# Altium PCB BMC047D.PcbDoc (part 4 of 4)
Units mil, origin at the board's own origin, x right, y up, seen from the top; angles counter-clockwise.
Board outline 4950 x 3450 mil, 6 copper layers (Top Layer, GND Layer 1, Signal Layer 1, Signal Layer 2, GND Layer 2, Bottom Layer), stack 60.7 mil thick; 323 components, 167 nets, 1114 pads, 795 vias.
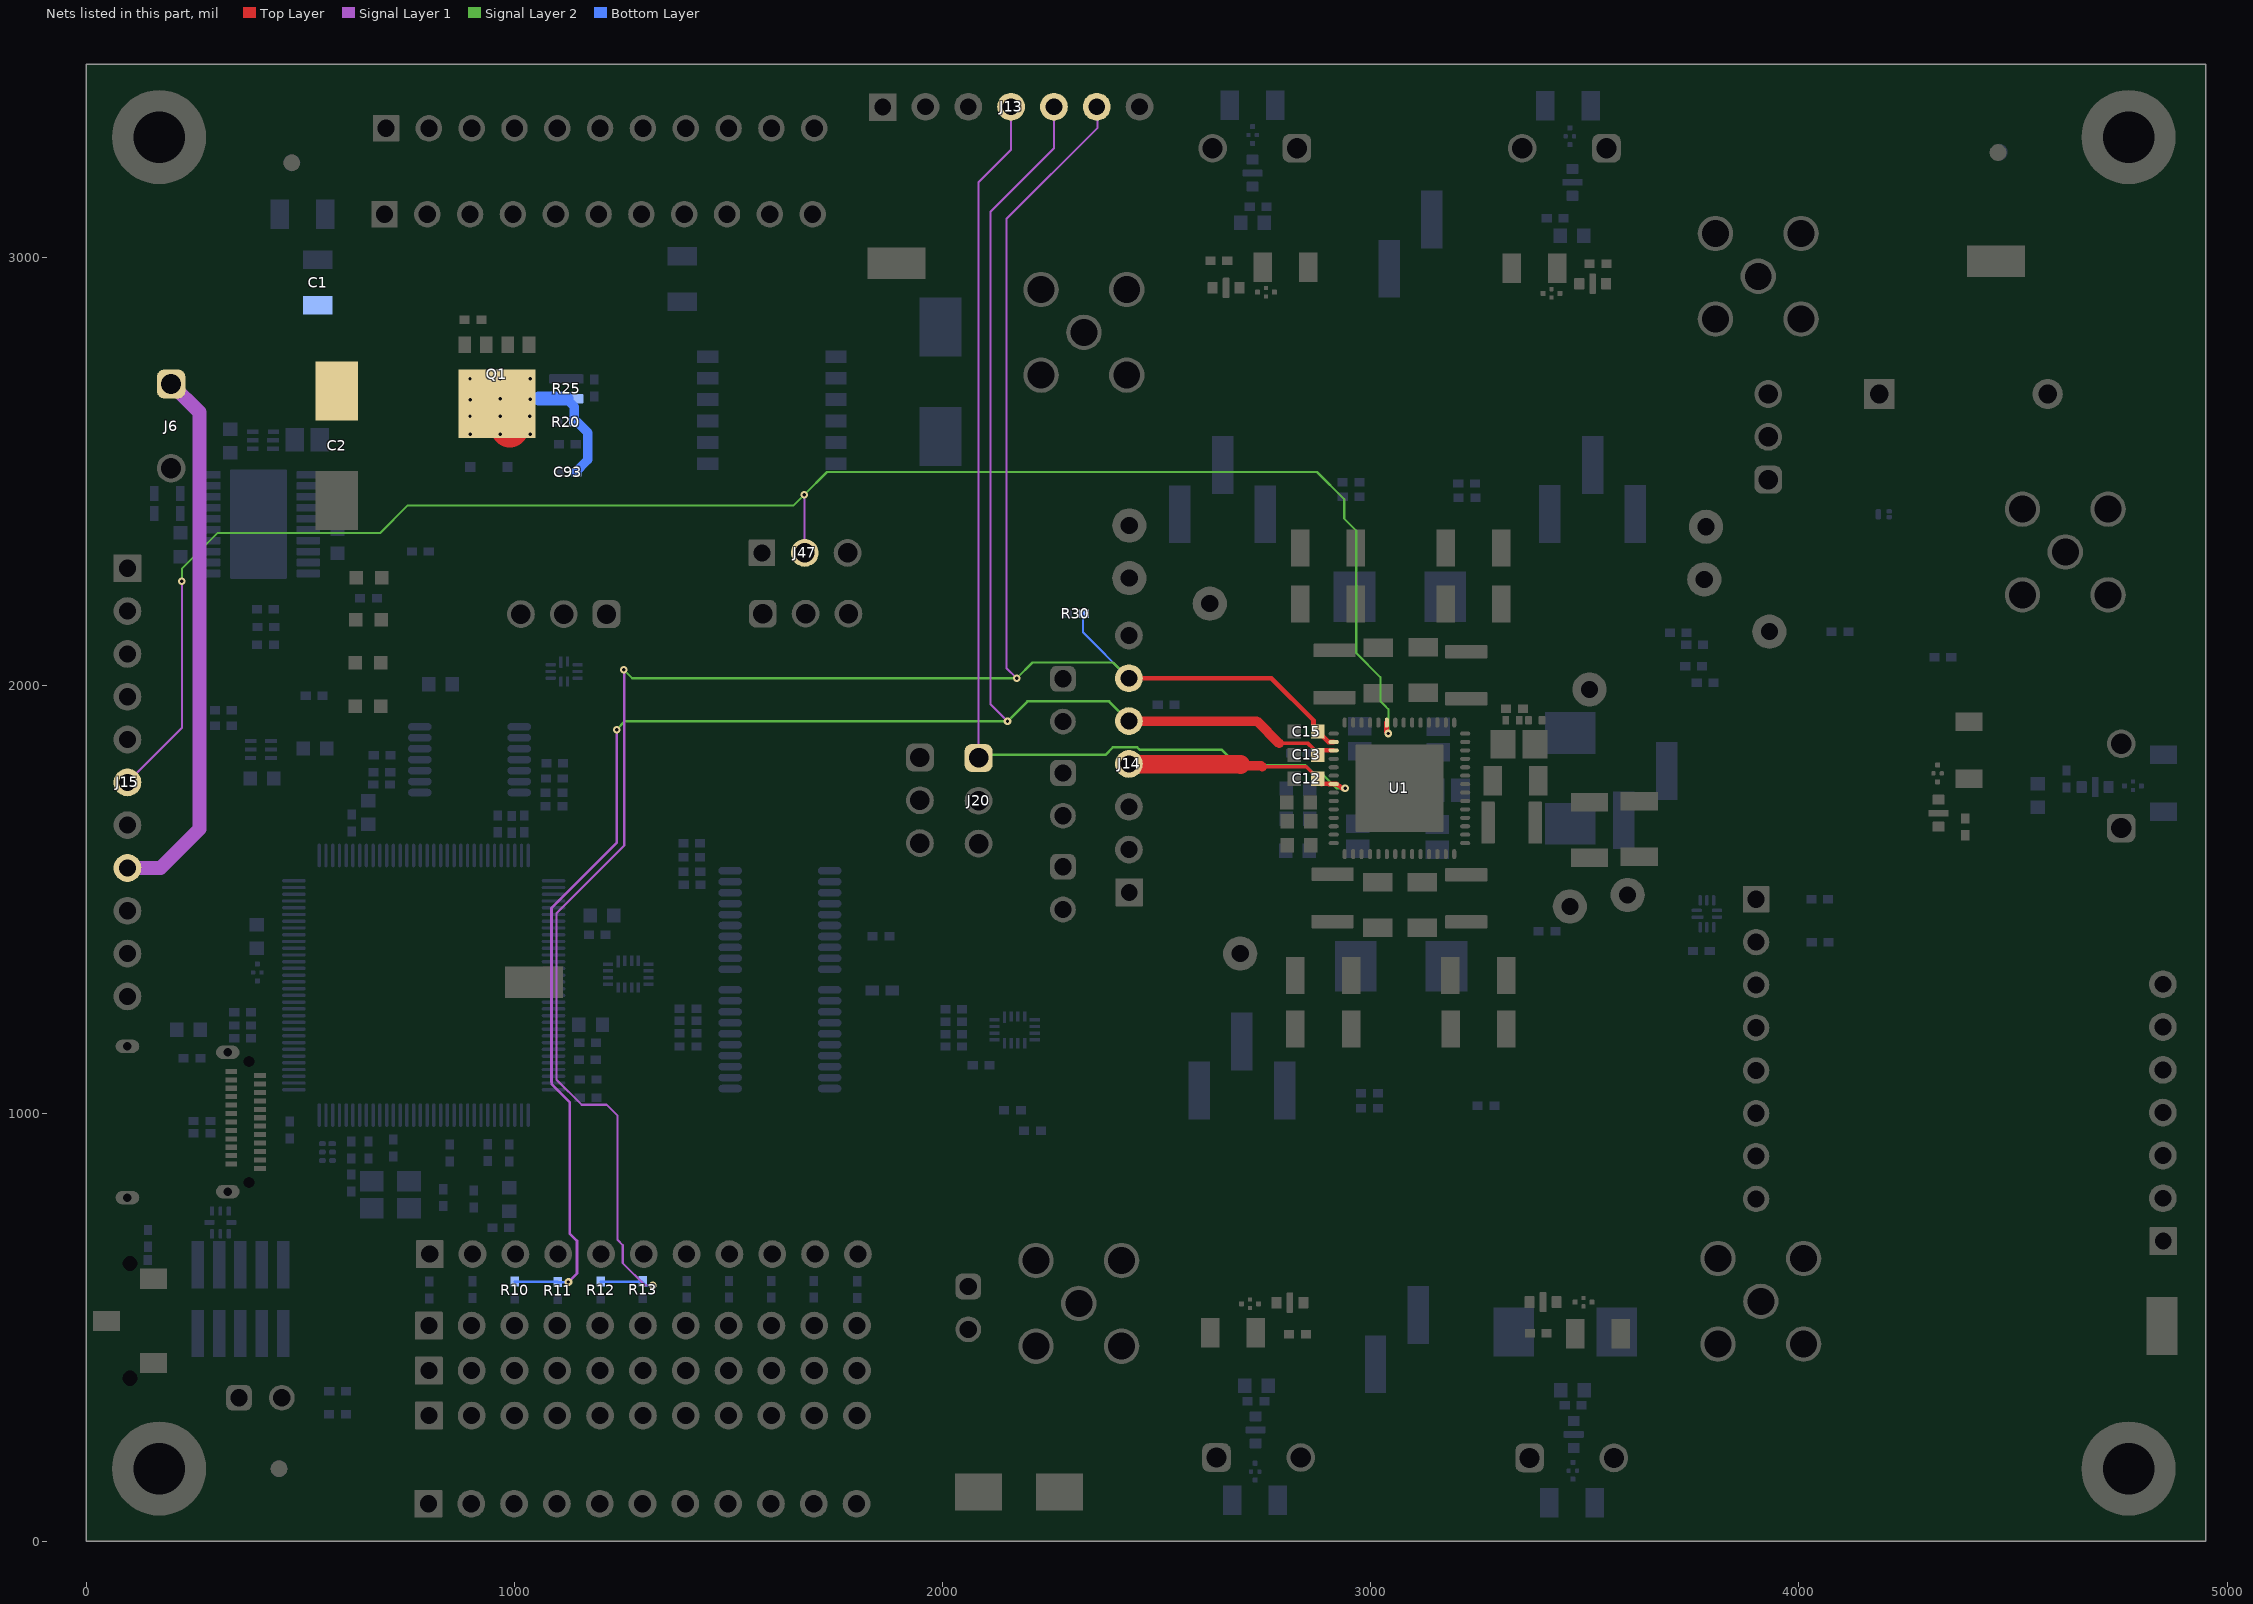
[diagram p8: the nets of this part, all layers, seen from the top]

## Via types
v1: diameter 18, hole 8, Top Layer to Bottom Layer, tented both sides, 520 vias
v2: diameter 22, hole 11, Top Layer to Bottom Layer, tented both sides, 196 vias
v3: diameter 22, hole 10, Top Layer to Bottom Layer, tented both sides, 36 vias
v4: diameter 19.68, hole 8, Top Layer to Bottom Layer, 21 vias
v5: diameter 19.68, hole 7.87, Top Layer to Bottom Layer, 9 vias
v6: diameter 19.68, hole 7.87, Top Layer to Bottom Layer, tented both sides, 6 vias
v7: diameter 20, hole 10, Top Layer to Bottom Layer, tented both sides, 3 vias
v8: diameter 18, hole 8, Top Layer to Bottom Layer, tented top, 2 vias
v9: diameter 18, hole 8, Top Layer to Bottom Layer, 1 vias
v10: diameter 66, hole 40, Top Layer to Bottom Layer, tented both sides, 1 vias

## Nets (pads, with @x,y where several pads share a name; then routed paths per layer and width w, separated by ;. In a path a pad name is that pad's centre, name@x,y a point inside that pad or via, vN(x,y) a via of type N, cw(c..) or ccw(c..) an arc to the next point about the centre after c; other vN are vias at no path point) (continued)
VOUT_LDO4: C12.1 J13.4 J14.4 J20.1 U1.7 | length 3086.8
  Top Layer w8: 2746.21,1809 2848.91,1809 C12.1@2877.56,1780.35
  Top Layer w11: C12.1@2876.62,1769.5 C12.1@2883.51,1769.5 ; C12.1@2884.72,1769.3 2885.23,1769.81 2901.38,1769.81 2901.89,1769.3 U1.7@2912.33,1769.3 ; U1.7@2912.61,1769.3 2920.7,1769.3 2924.62,1765.38 2926.26,1765.38 2932.65,1759 v1(2940,1759)
  Top Layer w22: 2608.31,1811.69 2743.53,1811.69 2746.21,1809
  Top Layer w44: J14.4@2435,1816 2696,1815
  Signal Layer 1 w5: J20.1@2084,1830 2084,1898.96 2084,2912.37 2084,3008.75 2084,3175.09 2160,3251.09 J13.4@2160,3351 ; J13.4@2160.2,3363.88 2160.2,3361.65 2165.5,3356.35 J13.4@2165.5,3347.65
  Signal Layer 2 w5: 2686.85,1813.37 2847.19,1813.37 2868.05,1792.51 2886.49,1792.51 2920,1759 v1(2940,1759)
  Signal Layer 2 w6: J20.1@2084,1830 2091,1837 2380,1837 2398,1855 2454.37,1855 2460.13,1849.24 2650.98,1849.24 2686.85,1813.37
VOUT_LDOVINT: C15.1 J13.6 J14.6 R12.2 R13.2 R30.1 U1.2 | length 5161
  Top Layer w11: J14.6@2435,2016 2768,2016 2866.24,1917.76 2866.24,1905.71 C15.1@2878.56,1893.4 ; C15.1@2881.5,1887 2901.23,1867.27 U1.2@2913.46,1867.27
  Signal Layer 1 w5: v1(1255,2036) 1256.5,2034.5 1256.5,1625.5 1098,1467 1098,1078.7 1156.79,1019.91 1215.23,1019.91 1241,994.15 1241,704 1253,692 1253,650 1305,598 v1(1323,598) ; v1(2173,2016) 2149.23,2039.77 2149.23,3089.23 2362,3302 J13.6@2362,3352.19
  Signal Layer 2 w5: v1@1254,2038 v1@1255,2038 ; v1(1255,2036) 1275,2016 v1(2173,2016) 2210.08,2053.08 2397.92,2053.08 J14.6@2435,2016
  Bottom Layer w5: R12.2@1201,606.69 1299,606.69 1307.69,598 v1(1323,598) ; R30.1@2327.69,2167.63 2327.69,2123.31 J14.6@2435,2016 J14.6@2434,2015
VOUT_LDOVRTC: C13.1 J13.5 J14.5 R10.2 R11.2 U1.3 | length 4769.3
  Top Layer w8: 2785.96,1864 2853.69,1864
  Top Layer w9: 2853.69,1864 2865.08,1852.62 2865.08,1849.23 C13.1@2868.96,1845.35
  Top Layer w11: C13.1@2875,1848 U1.3@2911,1848
  Top Layer w22: J14.5@2435,1916 2733.96,1916 2785.96,1864
  Signal Layer 1 w5: v1(2151.46,1915.46) 2111.71,1955.22 2111.71,3105.71 2260,3254 J13.5@2260,3351
  Signal Layer 1 w6: v1(1126,606) 1146,626 1146,702 1129,719 1129,1026.29 1086.71,1068.59 1086.71,1073.73 1086.5,1073.94 1086.5,1479.5 1239,1632 v1(1239,1896) v1@1239,1897
  Signal Layer 2 w6: v1@1239,1897 1257.46,1915.46 v1(2151.46,1915.46) 2198.02,1962.02 2388.98,1962.02 J14.5@2435,1916
  Bottom Layer w6: R10.2@1001,606.69 1100,606.69 R11.2@1101,605.69 1125.69,605.69 v1(1126,606)
VSYS: C1.1 C2.1 C93.1 J6.1 J15.8 Q1.5 R20.1 R25.1 | length 1570.3
  Top Layer w88: Q1.5@988.57,2599 Q1.5@988.57,2623.62
  Signal Layer 1 w33: J15.8@96,1573 173,1573 264,1664 264,2637.43 J6.1@198,2703.43
  Bottom Layer w22: R25.1@1121,2669.18 1139.68,2650.5 R20.1@1139.68,2614.39 1146.61,2614.39 1171,2590 1171,2526.32 C93.1@1141.68,2497
  Bottom Layer w33: 1056.82,2669.18 R25.1@1121,2669.18
  other v1: 896.38,2586 967,2586 1037,2586 896,2628 967,2628 1036,2628 896.38,2667 1037,2668 967,2669 896,2716 967,2716 1037,2716
VSYS_SENSE: J15.6 J47.2 U1.51 | length 4139.5
  Top Layer w11: U1.51@3036.63,1913 3036.63,1891.37 v1(3041,1887)
  Signal Layer 1 w5: J15.6@96,1773 223,1900 v1(223,2243) ; v1(1677,2445) 1677,2310 J47.2@1678,2309
  Signal Layer 2 w5: v1(223,2243) 223,2272 306,2355 686,2355 751,2420 1652,2420 v1(1677,2445) 1730,2498 2874.38,2498 2938,2434.38 2938,2389 2966,2361 2966,2074.98 3022.5,2018.48 3022.5,1962.5 3022.58,1962.5 3031.58,1953.5 ; 3032.5,1952.5 3041,1944 v1(3041,1887)
pads on no net: FID1.1 FID2.1 FID3.1 FID4.1 FID5.1 FID6.1 J22.A2 J22.A3 J22.A8 J22.A10 J22.A11 J22.ALIGN1 J22.ALIGN2 J22.B2 J22.B3 J22.B8 J22.B10 J22.B11 LBL1.0 Q2.0 S1.MH1 S1.MH2 SH-J1.0 SH-J2.0 SH-J3.0 SH-J4.0 SH-J5.0 SH-J6.0 SH-J7.0 SH-J8.0 SH-J9.0 SH-J10.0 SH-J11.0 SH-J12.0 SH-J13.0 SH-J14.0 SH-J15.0 SH-J16.0 U3.5 U3.11 U3.12 U3.13 U3.14 U3.15 U3.18 U3.19 U3.20 U3.21 U3.27 U3.32 U3.33 U3.34 U3.35 U3.36 U3.37 U3.38 U3.40 U3.42 U3.43 U3.44 U3.45 U3.46 U3.49 U3.53 U3.54 U3.56 U3.57 U3.65 U3.66 U3.67 U3.72 U3.73 U3.74 U3.75 U3.76 U3.77 U3.83 U3.84 U3.85 U3.86 U3.102 U3.103 U3.107 U3.108 U3.109 U3.110 U3.111 U3.112 U3.116 U3.117 U3.118 U3.119 U3.120 U3.121 U3.124 U3.125 U3.126 U3.127 U4.2 U5.5 U7.2 U7.10 U10.2 U10.10 U11.1 U11.4 U11.8 U11.11 U13.5 U14.21@402.16,2376 Y2.2 Y2.4
copper on no net: | length 3928.2
  Top Layer w22: 2831.09,2535.41 2831.5,2535
  Signal Layer 1 w6: v1(765,1699.35) 767.3,1697.05 770.99,1697.05 875.42,1592.62 v1(875.42,927.27) ; v1(1154.57,1491.03) 1176,1469.6 1176,1420.04 1143,1387.04 1143,1338.96 1160.72,1321.24 1198.42,1321.24 1214.52,1305.14 1214.52,1246.48 1240,1221 1240,1129.12 1230.04,1119.17 v1(1230.04,1070) ; 2332,857 2333,858
  Signal Layer 1 w66: 2212,1633 2212,1733 2212,1833
  Signal Layer 2 w6: v1(301,1204) 458.48,1204 588.48,1074 745.96,1074 762.31,1090.35 v1(875.42,1090.35) ; v1(698.83,1695.55) 700.72,1697.45 763.1,1697.45 v1(765,1699.35) ; v1(875.42,927.27) 908.69,894 1180.4,894 v1(1180.5,893.9) ; v1(1230.04,1070) 1232.04,1068 v1(1291.5,1068) ; 1289,1497.15 1289,1498 ; v1@1612.78,1049.22 1896.82,1049.22 1951.89,994.15 v1(2010,994.15)
  Bottom Layer w6: 325.5,1228.5 325.5,1236 ; v1@691.94,1699.19 695.58,1695.55 v1(698.83,1695.55) ; v1(1154.57,1491.03) 1191.76,1491.03 1204.19,1478.61 ; v1(1180.5,893.9) 1293.09,893.9 1370.42,971.23 1370.42,990.69 1553.2,990.69 v1(1609,1046.49) ; 1209.5,1106.46 1209.5,1113 ; v1(1291.5,1068) 1370.03,989.47
  Bottom Layer w66: 2212,1633 2212,1733 2212,1833

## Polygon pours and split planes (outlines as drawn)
GND on Top Layer "GND_L01_P792" (solid, pour order 792): 1.93,3440 4931.93,3440 4931.93,10 1.93,10 1.93,1419 1.93,3421
VCCA on Top Layer "VCCA_L01_P623" (solid, remove dead copper, pour order 623): 613.8,3172.16 1570.65,3172.16 1837.81,2905.01 2364,2378.82 2364,1447.88 1877.08,1447.88 571.3,2753.66 571.3,3123.67 613.8,3166.16
VOUT_B1 on Top Layer "VOUT_B1_L01_P791" (solid, remove dead copper, pour order 791): 3728.63,8.19 3067.37,8.19 3067.37,1458.19 3728.63,1458.19
VOUT_B2 on Top Layer "VOUT_B2_L01_P790" (solid, remove dead copper, pour order 790): 3061.85,8.19 2400.59,8.19 2400.59,1458.19 3061.85,1458.19
no net on Top Layer "NONET_L01_P598" (solid, remove dead copper, pour order 598): 2841.83,471.19 2841.83,515.59 2823.07,534.35 2823.07,577.65 2818.5,582.22 2800.23,582.22 2800.23,546.23 2786,532 2726.93,532 2726.93,570.34 2722.89,574.38 2714.28,574.38 2678.93,539.03 2678.93,452.76 2695.69,436 2806.64,436
no net on Top Layer "NONET_L01_P589" (solid, remove dead copper, pour order 589): 4409.81,1671.87 4365.41,1671.87 4346.65,1690.63 4303.35,1690.63 4298.78,1695.2 4298.78,1713.47 4337.47,1713.47 4352,1728 4349,1731 4349,1784 4315.12,1784 4304,1795.12 4304,1805.5 4341.35,1805.5 4342.36,1806.52 4434.48,1806.52 4445,1796 4445,1707.06
VCCA on Top Layer "VCCA_L01_P749" (solid, remove dead copper, pour order 749): 2953,1886.81 2953,1933.52 2967.35,1947.87 2986.47,1947.77 2993,1941.24 2993,1880.79 2987,1874.79 2965.02,1874.79
VCCA on Top Layer "VCCA_L01_P747" (solid, remove dead copper, pour order 747): 2942,1643 2986,1643 2990,1639 2990,1571 2982.92,1563.92 2948.5,1563.92 2940,1572.42 2940,1642.4 2941.4,1642.4
VCCA on Top Layer "VCCA_L01_P745" (solid, remove dead copper, pour order 745): 3184,1767 3187.6,1770.6 3250.34,1770.6 3257.94,1763 3257.94,1733.94 3253,1729 3177.36,1729 3174,1732.36 3174,1768 3177,1771 3177.19,1770.81 3188,1770.81
VCCA on Top Layer "VCCA_L01_P737" (solid, remove dead copper, pour order 737): 3179,1642.4 3179,1579.34 3170.66,1571 3138,1571 3137,1572 3137,1640.9 3138.5,1642.4
SW_B4 on Top Layer "SW_B4_L01_P705" (solid, remove dead copper, pour order 705): 2963,1983.81 2959.81,1987 2866.29,1987 2863.29,1984 2863.56,1983.73 2863.56,1954 2916.56,1901 2959,1901 2963,1905
SW_B2 on Top Layer "SW_B2_L01_P703" (solid, remove dead copper, pour order 703): 2961,1613.94 2960.81,1532.46 2957,1529 2880.59,1529.04 2870,1539.88 2870,1574 2909.94,1613.94
SW_B1 on Top Layer "SW_B1_L01_P701" (solid, remove dead copper, pour order 701): 3231,1615 3274,1572 3274,1533 3273.42,1533 3266.42,1526 3175.04,1526 3175.04,1527.69 3171,1531.73 3171,1610.96 3175.04,1615
SW_B3 on Top Layer "SW_B3_L01_P699" (solid, remove dead copper, pour order 699): 3172.95,1980.85 3172.95,1900 3222.27,1900 3273,1950.73 3273,1980.85
VOUT_B3 on Top Layer "VOUT_B3_L01_P691" (solid, remove dead copper, pour order 691): 3067,3439 3067,2034.54 3712,2034.54 3710,2036.54 3710,3439
no net on Top Layer "NONET_L01_P594" (solid, remove dead copper, pour order 594): 2651.63,3025.28 2807.68,3023.19 2807.68,2939.59 2649.97,2940.35 2649.97,3023.62
VSYS on Top Layer "VSYS_L01_P617" (solid, remove dead copper, pour order 617): 173,2940 770,2940 840,2870 840,2773 873,2740 1048.79,2740 1068.25,2720.54 1068.25,2555.25 1053,2540 747.63,2540 747.63,2541.3 720,2568.93 720,2606 672.76,2640 167,2640 167,2643 150,2660 150,2917
no net on Top Layer "NONET_L01_P597" (solid, remove dead copper, pour order 597): 2484.6,1645 2785.37,1645 2795.44,1634.93 2795.44,1608.92 2481.08,1608.92 2480,1610 2480,1641 2480.6,1641
VOUT_B5 on Top Layer "VOUT_B5_L01_P618" (solid, remove dead copper, pour order 618): 3322.58,2028 4940,2028 4940,1474 3322.58,1474
VOUT_B4 on Top Layer "VOUT_B4_L01_P619" (solid, remove dead copper, pour order 619): 3076,2045.57 2415.45,2045.57 2415.45,3440 3076,3440
SW_B5 on Top Layer "SW_B5_L01_P596" (solid, remove dead copper, pour order 596): 3207,1734 3291.52,1734 3318.07,1707.45 3318.07,1649.55 3297.52,1629 3242,1629 3239.67,1631.33 3239.67,1714.33 3233,1721 3212,1721 3207,1726
no net on Top Layer "NONET_L01_P611" (solid, remove dead copper, pour order 611): 2937.2,2620 2955.2,2638 3239,2638 3255,2622 3255,2524 3237,2506 2956,2506 2937.2,2526
no net on Top Layer "NONET_L01_P603" (solid, remove dead copper, pour order 603): 2800,1418.29 2784.71,1403 2784.71,1197 2801,1180.71 2845,1180.71 2860.29,1196 2860.29,1402 2844,1418.29
no net on Top Layer "NONET_L01_P604" (solid, remove dead copper, pour order 604): 3293,1417.29 3277.71,1402 3277.71,1196 3294,1179.71 3338,1179.71 3353.29,1195 3353.29,1401 3337,1417.29
no net on Top Layer "NONET_L01_P605" (solid, remove dead copper, pour order 605): 3283.96,2343.5 3268.67,2328.2 3268.67,2122.2 3284.96,2105.91 3328.96,2105.91 3344.25,2121.2 3344.25,2327.2 3327.96,2343.5
no net on Top Layer "NONET_L01_P601" (solid, remove dead copper, pour order 601): 2810.04,2343.29 2794.75,2328 2794.75,2122 2811.04,2105.71 2855.04,2105.71 2869.78,2120.45 2869.78,2327.55 2854.04,2343.29
no net on Top Layer "NONET_L01_P599" (solid, remove dead copper, pour order 599): 3369.87,474.19 3369.87,518.59 3388.63,537.35 3388.63,580.65 3393.2,585.22 3411.47,585.22 3411.47,548.53 3425,535 3489,535 3489,575.88 3493.12,580 3500.46,580 3515,565.46 3515,449.93 3504.07,439 3405.06,439
no net on Top Layer "NONET_L01_P600" (solid, remove dead copper, pour order 600): 3545.71,3008.81 3545.71,2964.41 3526.95,2945.65 3526.95,2902.35 3522.38,2897.78 3504.11,2897.78 3504.11,2936.47 3475.06,2936.47 3433.58,2936.47 3433.58,2914.12 3422.47,2903 3412.08,2903 3412.08,2940.35 3411.06,2941.36 3411.06,3033.48 3421.58,3044 3510.52,3044
no net on Bottom Layer "NONET_L06_P665" (solid, remove dead copper, pour order 665): 2945.85,1872.71 3185.53,1872.71 3188.25,1870 3188.25,1651.9 2944,1651.9 2945.85,1653.75
VCCA on Bottom Layer "VCCA_L06_P659" (solid, pour order 659): 613.8,3166.16 601.2,3153.57 601.2,2198.76 1399.28,1400.69 3405.96,1400.69 3405.96,2140.96 3401.95,2144.97 3397.94,2140.96 2557.12,2140.96 1528.8,3169.28
GND on Bottom Layer "GND_L06_P658" (solid, pour order 658): 4531.07,2099.1 4931.1,2099.1 4936.08,2094.12 4936.08,1766.46 4931.1,1750.44 4538.86,1750.44
GND on Bottom Layer "GND_L06_P806" (solid, pour order 806): 10,3440 4940,3440 4940,10 10,10
MCUVCC on Bottom Layer "MCUVCC_L06_P802" (solid, remove dead copper, pour order 802): 268.36,2201.12 248.36,2181.12 248.36,473.12 268.36,453.12 758.36,453.12 758.36,505.65 1424.05,1171.33 1424.05,2179.53 1402.45,2201.12 1401.65,2200.32 268.36,2200.32
VOUT_B5 on Bottom Layer "VOUT_B5_L06_P803" (solid, remove dead copper, pour order 803): 3719.97,2099.1 4938.59,2099.1 4938.59,1458.13 3721.29,1458.13 3719.11,1460.31 3719.97,1461.17
VOUT_B1 on Bottom Layer "VOUT_B1_L06_P671" (solid, remove dead copper, pour order 671): 3405.96,1726.52 3737.85,1726.52 3737.85,537.27 3405.97,537.27
VOUT_B3 on Bottom Layer "VOUT_B3_L06_P668" (solid, remove dead copper, pour order 668): 3409.7,2162.38 3733.15,2162.38 3733.15,1739.19 3726.12,1732.15 3409.7,1732.15
VOUT_B4 on Bottom Layer "VOUT_B4_L06_P785" (solid, remove dead copper, pour order 785): 2503.17,2138.17 2503.17,3060 2723.78,3060 2725,3061.22 2725,3440 3079,3440 3080.73,3438.27 3080.73,2138.17 2505.83,2138.17 2505.05,2137.39
VOUT_B3 on Bottom Layer "VOUT_B3_L06_P666" (solid, remove dead copper, pour order 666): 3750.8,3030 3750.99,3440 3466.54,3440 3466.54,3029.55 3469.5,3026.58 3472.93,3030
VSYS on Bottom Layer "VSYS_L06_P670" (solid, remove dead copper, pour order 670): 1060,2910 1080,2890 1080,2551.34 1062.66,2534 756.76,2534 736.76,2554 736.76,2614.08 735.92,2614.08 720,2630 160,2630 140,2650 140,2883 167,2910
no net on Bottom Layer "NONET_L06_P660" (solid, remove dead copper, pour order 660): 3293,1360 3338,1360 3338,1195 3337,1196 3293,1196
no net on Bottom Layer "NONET_L06_P661" (solid, remove dead copper, pour order 661): 2800,1403 2844.86,1403 2844.86,1196.14 2844,1197 2800,1197
VOUT_B1 on Bottom Layer "VOUT_B1_L06_P672" (solid, remove dead copper, pour order 672): 3427.81,1402 3426.81,1403 3080,1403 3080,12.16 3474,12.16 3475,13.16 3475,1401 3474,1402
VOUT_B2 on Bottom Layer "VOUT_B2_L06_P674" (solid, remove dead copper, pour order 674): 3054.54,1404.8 2541.08,1404.8 2538.35,1402.07 2538.35,12.16 2731,12.16 2731,430 3054.54,430
no net on Bottom Layer "NONET_L06_P669" (solid, remove dead copper, pour order 669): 3689,537 3689,29 3680,20 3407.24,20 3407.24,531.71 3412.54,537
VSYS on Bottom Layer "VSYS_L06_P662" (solid, remove dead copper, pour order 662): 1071,2735 1071,2558 1072,2557 1069,2554 856,2554 851,2559 851,2731.07 854.93,2735
VOUT_B3 on Bottom Layer "VOUT_B3_L06_P781" (solid, remove dead copper, pour order 781): 3092.1,2141.07 3753.31,2141.02 3753.31,3030 3092.77,3030
VOUT_B1 on Bottom Layer "VOUT_B1_L06_P664" (solid, remove dead copper, pour order 664): 3388.69,1560.53 3389.21,1560 3647.22,1560 3647.22,1407.09 3626.83,1386.71 3388.69,1386.71
VCCA on Signal Layer 1 "VCCA_L03_P634" (solid, remove dead copper, pour order 634): 3189.89,2045.57 3311,1924.46 3311,1588 3283,1560 2198,1560 2173,1585 2170,1585 2173.21,2045.57
GND on Signal Layer 1 "GND_L03_P797" (solid, pour order 797): 10,3440 4940,3440 4940,10 10,10
VCCA on Signal Layer 1 "VCCA_L03_P627" (solid, remove dead copper, pour order 627): 3179,1735 3179,1769.1 3182.9,1773 3231,1773 3248.24,1755.76 3248.24,1739.24 3238.93,1729.93 3184.07,1729.93
VCCA on Signal Layer 1 "VCCA_L03_P632" (solid, remove dead copper, pour order 632): 3159.02,1624 3159.02,1589.94 2984,1589.94 2984,1624
VCCA on Signal Layer 1 "VCCA_L03_P633" (solid, remove dead copper, pour order 633): 3152.02,1934 3152.02,1894.41 2977,1894.41 2977,1930 2981,1934
VCCA on Signal Layer 1 "VCCA_L03_P629" (solid, remove dead copper, pour order 629): 2944,1948 2998,1948 3001,1945 3001,1871 2995,1865 2946,1865 2939,1872 2939,1943
VCCA on Signal Layer 1 "VCCA_L03_P631" (solid, remove dead copper, pour order 631): 3135,1952.47 3189,1952.47 3192,1949.47 3192,1875.47 3186,1869.47 3137,1869.47 3130,1876.47 3130,1947.47
VCCA on Signal Layer 1 "VCCA_L03_P630" (solid, remove dead copper, pour order 630): 3135,1655 3189,1655 3192,1652 3192,1578 3186,1572 3137,1572 3130,1579 3130,1650
VCCA on Signal Layer 1 "VCCA_L03_P628" (solid, remove dead copper, pour order 628): 2936,1651 2990,1651 2993,1648 2993,1574 2987,1568 2938,1568 2931,1575 2931,1646
GND on GND Layer 1 "GND_L02_P794" (solid, pour order 794): 10,3440 4940,3440 4940,10 10,10 10,485.76
GND on GND Layer 2 "GND_L05_P799" (solid, pour order 799): 10,3440 4940,3440 4940,10 10,10
GND on Signal Layer 2 "GND_L04_P798" (solid, pour order 798): 10,3440 4940,3440 4940,10 10,10

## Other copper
Top Layer:
  pour cut-out: 4472.2,2209.3 ccw(c4522.2,2209.3) 4522.2,2159.3 ccw(c4522.2,2209.3) 4572.2,2209.3 ccw(c4522.2,2209.3) 4522.2,2259.3 ccw(c4522.2,2209.3)
  pour cut-out: 4672.2,2209.3 ccw(c4722.2,2209.3) 4722.2,2159.3 ccw(c4722.2,2209.3) 4772.2,2209.3 ccw(c4722.2,2209.3) 4722.2,2259.3 ccw(c4722.2,2209.3)
  pour cut-out: 4672.2,2409.3 ccw(c4722.2,2409.3) 4722.2,2359.3 ccw(c4722.2,2409.3) 4772.2,2409.3 ccw(c4722.2,2409.3) 4722.2,2459.3 ccw(c4722.2,2409.3)
  pour cut-out: 4472.2,2409.3 ccw(c4522.2,2409.3) 4522.2,2359.3 ccw(c4522.2,2409.3) 4572.2,2409.3 ccw(c4522.2,2409.3) 4522.2,2459.3 ccw(c4522.2,2409.3)
  pour cut-out: 3056.83,1022 3063.64,1012.15 3062.81,1004.74 3058,998 3044.29,998 3038.29,1004 3038.29,1016.24 3044.05,1022
  pour cut-out: 3318.65,1029.85 3324.2,1021.81 3324.2,1011.85 3318.89,1005.85 3304.65,1005.85 3298.65,1011.85 3298.65,1024.09 3304.41,1029.85
  pour cut-out: 3253.24,2505 3258.83,2496.9 3257.81,2487.74 3253,2481 3239.29,2481 3233.29,2487 3233.29,2499.24 3239.05,2505
  pour cut-out: 2921,2509.91 2947,2509.91 2947,2485.91 2921,2485.91
  pour cut-out: 2898.29,1784.71 2907,1776 2942.91,1776 2950.63,1783.71 2950.63,1819.74 2946.42,1823.95 2907.95,1823.95 2898.29,1814.29
  text ".Layer_Name" at 576,-862 h60
Signal Layer 1:
  text ".Layer_Name" at 569,-858 h60
Signal Layer 2:
  text ".Layer_Name" at 576,-863 h60
GND Layer 1:
  pour cut-out: 3389,565 3395,571 3407.88,571 3413,565.88 3413,554 3406,547 3396,547 3389,554
  pour cut-out: 2901,2445 2908,2452 2921.25,2452 2927,2446.25 2927,2435 2919,2427 2909,2427 2901,2435
  text ".Layer_Name" at 574,-858 h60
GND Layer 2:
  text ".Layer_Name" at 576,-862 h60
Bottom Layer:
  rectangle net VOUT_B3: 3407,1745.54 3527,1839.39
  rectangle net VOUT_B4: 2999.69,2142 3045.93,2267
  rectangle net VOUT_B2: 2994.37,1284 3055.91,1404
  rectangle net VOUT_B1: 3080.04,1283 3153,1404
  pour cut-out: 3274.31,1037.86 3325.69,1037.86 3325.69,999.86 3274.31,999.86
  pour cut-out: 3002.62,1062.28 3067.58,1062.28 3067.58,993.76 3002.62,993.76
  pour cut-out: 3224,2452.84 3224,2506.76 3262,2506.76 3262,2452.84
  pour cut-out: 2952,2509 2952,2458.24 2914,2458.24 2914,2509
  pour cut-out: 4360.91,50 4360.91,149.41 3849.09,149.41 3849.09,50
  text "©" at 3860,65 h105
  text "2019" at 3949,65 h60
  text "TI" at 4225,65 h60
  text ".Layer_Name" at 576,-859 h60

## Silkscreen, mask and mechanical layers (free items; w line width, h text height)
Top Overlay:
  lines w4: 2782,1406 3418.74,1407.53 ; 3419.73,1408.52 3419.73,2116.24
  lines w5: 1185.53,1687.28 1860.15,1687.28 ; 1186.53,1785.28 1859.69,1785.28 ; 1186.53,1875.28 1861.15,1875.28 ; 1243.78,1600.28 1244.78,1928.28 ; 1521.05,1929.28 1523.05,1601.28 ; 1861.15,1662.28 1861.15,1664.28 ; 1927,986 2546,986 ; 1927,1046 2546,1046 ; 1927,1106 2546,1106 ; 1927,1166 2547,1166 ; 1927,1226 2547,1226 ; 1927,1286 2547,1286 ; 2077,926 2077,1341 ; 2227,926 2227,1340 ; 2380.17,1341 2382,926 ; 2546,926 1927,926 1927,1341 2547,1341 2547,927 ; 2547,1073 2547,1075 ; 2782,1406 2782,2074.48 2808.45,2100.92 2821.83,2113.56 3419.73,2116.24 ; 3561,1781 3561,1781.2 ; 1184.53,1601.28 1184.53,1930.28 1861.15,1930.28 1859.75,1601.28 1184.53,1601.28
  lines w6: 3420,2070 3700,2070
  lines w9: 940,740 940,960 ; 1240,740 1240,1080 ; 1440,736 1440,1080 ; 1640,736 1640,1060 ; 1840,736 1840,1100
  lines w10: 787.33,747.25 cw(c845,735) 902.97,745.73
  lines w11: 383,2876 498,2876 ; 443,2822.26 443,2930 443,2911 ; 701.62,3345 716.62,3360 1376.19,3360 1392.19,3344 ; 712.19,3150 728.31,3164.23 1388.31,3164.23 1404.47,3150 ; 1480.95,3150 1495.95,3165 1693.33,3165 1709.33,3149 ; 1487.26,3345 1502.26,3360 1699.64,3360 1715.64,3344 ; 2316,2116 2381.79,2116 ; 2416,214 2496.78,214 ; 2430,3077 2488.5,3077 ; 2456,167 2456,257 ; 2965,200.88 3040,200.88 ; 2996,3077 3083.07,3077 ; 3038,3034 3038,3119 ; 3145,206.94 3226.06,206.94 ; 3158,3250 3226.07,3250 ; 3187.3,165 3187.3,250 ; 3685,3249 3774,3248 ; 3690,206.94 3781.06,206.94 ; 3731,3204 3731,3286 ; 4685,1490 4775,1490 ; 4730,1449 4730,1525 ; 4740,1985 4740,2055
  lines w16: 446,2334 446,2427
  text "CS1, 3, 5" at 1460.45,3380 h72.83
  text "GND" at 967,3369 h72.83
  text "BUCK4" at 2950,3360.51 h72.83
  text "BUCK3" at 3674,3359 h72.83
  text "LDO1" at 1845.02,3291 h55 r270
  text "LDO2" at 1949.19,3291 h55 r270
  text "LDO3" at 2050.25,3291 h55 r270
  text "LDO4" at 2147.66,3291 h55 r270
  text "VINT" at 2348.68,3291 h55 r270
  text "GND_S" at 2447.02,3290.65 h55 r270
  text "VRTC" at 2251.26,3290 h55 r270
  text "CS0, 2, 4" at 1456.17,3186 h72.83
  text "VCCA" at 946,3175 h72.83
  text "LDO OUTPUTS SENSE" at 1811.23,3044 h72.83
  text "GND" at 4394,3043 h72.83
  text "C-Cell" at 4180,2927.88 h66
  text "VSYS" at 136.17,2923.84 h72.83
  text "GND" at 1825.41,2868.35 h72.83
  text "VBACKUP" at 3823.34,2688.78 h55 r270
  text "BMC047D" at 1527.7,2408 h99
  text "VCCA" at 2210.62,2354.82 h66
  text "VIO_IN" at 3837.91,2350 h72.83
  text "VIO_IN Select" at 942,2315 h66
  text "nINT" at 241,2247 h77
  text "FB_B4" at 2200,2230.23 h66
  text "1.8V" at 955,2229 h77
  text "3.3V" at 1157,2228 h77
  text "FB_B3" at 3844.27,2225.27 h66
  text "BUCK5" at 4824,2184 h72.83 r270
  text "EN_DRV" at 170,2150 h77
  text "AMUXOUT" at 1998,2096 h72.83
  text "16x18 mm" at 3429,2078 h66
  text "Slave" at 1520,2069 h66
  text "Master" at 1699.64,2066 h66
  text "nRSTOUT" at 167.93,2052 h77
  text "SYNCCLKIN" at 3754,2022 h72.83
  text "M/S Select" at 1545.51,1995 h66
  text "nPWRON" at 167.93,1954 h77
  text "J19" at 1355.59,1888.28 h50
  text "J20" at 1662.38,1886.28 h50
  text "OVPGDRV" at 167.93,1851 h77
  text "1" at 1207.53,1809.28 h55
  text "LDO4_IN_S" at 1253.53,1809.28 h55
  text "LDO4_OUT_S" at 1530.53,1809.28 h55
  text "VSYS_SENSE" at 167,1751 h77
  text "2" at 1201.53,1715.59 h55
  text "GND_S" at 1300.53,1716.28 h55
  text "GND_S" at 1610.4,1716.28 h55
  text "V3V3" at 166,1654 h72.83
  text "LDO3_OUT_S" at 1530.11,1630.28 h55
  text "LDO3_IN_S" at 1252.53,1626.28 h55
  text "3" at 1201.53,1619.28 h55
  text "VSYS" at 168,1550 h77
  text "SCLK_SPMI" at 3949,1483 h50
  text "V5V0" at 168,1451 h77
  text "SDATA_SPMI" at 3944,1384.02 h50
  text "SCL2/CS" at 167.93,1352 h77
  text "Input" at 2252,1300 h55
  text "Output" at 2387,1300.11 h55
  text "LDO #" at 1942,1295.11 h50
  text "VCCA" at 2092,1295.11 h50
  text "GND_S" at 4610,1290 h55
  text "nPWRON_S" at 3952,1288 h50
  text "BUCK OUTPUTS" at 4440,1265 h72.83 r270
  text "GPIO1" at 167.93,1251 h77
  text "VINT" at 1948,1238 h55
  text "N/A" at 2111,1238 h55
  text "J14-6" at 2402,1236 h55
  text "N/A" at 2258,1234 h55
  text "GND" at 978,1217 h72.83
  text "SDA1/SDI" at 3949,1184 h55
  text "VCCA_S" at 4580,1184 h55
  text "J14-5" at 2402,1181 h55
  text "N/A" at 2111,1179 h55
  text "N/A" at 2259,1179 h55
  text "VRTC" at 1940,1178 h55
  text "J14-4" at 2402,1121 h55
  text "4" at 1985,1117 h55
  text "J18-1" at 2090,1116.13 h55
  text "J18-2" at 2244.89,1116.13 h55
  text "SDA2/SDO" at 3948,1083 h55
  text "VOUT_B5" at 4554,1082 h55
  text "J14-3" at 2402,1061 h55
  text "3" at 1986,1057 h55
  text "J17-1" at 2091,1057 h55
  text "J17-2" at 2244,1057 h55
  text "J14-2" at 2402,1001 h55
  text "2" at 1987,997 h55
  text "J16-1" at 2092,997 h55
  text "J16-2" at 2244,997 h55
  text "SCL1/SCK" at 3952,983 h55
  text "VOUT_B4" at 4554,982 h55
  text "J16-1" at 2091,941 h55
  text "J16-2" at 2241,936 h55
  text "J14-1" at 2402,936 h55
  text "1" at 1987,934 h55
  text "SCL2/CS" at 3952,886 h55
  text "VOUT_B3" at 4554,880 h55
  text "SPI_EN" at 871,810 h72.83 r90
  text "VIO_IN" at 3953,786 h55
  text "VOUT_B2" at 4554,782 h55
  text "GPIO3" at 1421,752 h72.83 r90
  text "SDA2/SDO" at 1223,750 h72.83 r90
  text "nERR_SOC" at 1323,750 h72.83 r90
  text "nERR_MCU" at 1523,750 h72.83 r90
  text "GPIO7" at 1621,750 h72.83 r90
  text "GPIO2" at 1129,749 h72.83 r90
  text "TRIG_WDG" at 1724,749 h72.83 r90
  text "GPIO11" at 1823,747 h72.83 r90
  text "TRIG_WDG" at 1030,743 h72.83 r90
  text "GND" at 45,712 h66
  text "VOUT_B1" at 4554,685.61 h55
  text "GPIO Float" at 1982,663 h50
  text "PWR_BUT" at 226,652.8 h60 r270
  text "Option" at 544,650 h77
  text "PU" at 628,473 h77
  text "GND" at 4638,441 h72.83
  text "RSTOUT" at 312,402 h55
  text "GPIO" at 563,372 h72.83
  text "BUCK2" at 2965,360 h72.83
  text "BUCK1" at 3690,352 h72.83
  text "VCCA" at 25,285 h66
  text "PD" at 631,267 h77
  text "MCU_RST" at 2040,220 h66
  text "1" at 788,169 h72.83
  text "2" at 890,165 h72.83
  text "3" at 990,165 h72.83
  text "4" at 1085,165 h72.83
  text "5" at 1185,165 h72.83
  text "6" at 1285,165 h72.83
  text "7" at 1385,165 h72.83
  text "8" at 1485,165 h72.83
  text "9" at 1580,165 h72.83
  text "10" at 1665,165 h72.83
  text "11" at 1770,165 h72.83
  text "GPIO" at 553,60 h72.83
  text ".Layer_Name" at 573,-860 h60
Bottom Overlay:
  lines w5: 2645,711.5 3545,711 ; 2645,859.5 3544,859 ; 2645,907.5 3546,906 ; 2647,758.5 3546,758 ; 2647,811.5 3545,811 ; 2714,658.5 2714,962.5 ; 2791,658.5 2791,962.5 ; 2864,658.5 2864,963.5 ; 2975,660.5 2975,961.5 ; 3085,658.5 3085,962.5 ; 3198,659.26 3198,963.26 ; 3296,659 3296,963 ; 2645,658.5 2645,962.5 3546,963 3546,659 2645,658.5
  lines w6: 1135,1816 1135,1706.8 1164.2,1706.8 1186,1706.8 1186.6,1899.2
  text "S" at 2574,2549 h72.83
  text "M" at 2784.71,2549 h72.83
  text "M" at 3650,2549 h72.83
  text "S" at 3424,2547 h72.83
  text "S" at 2608.24,1176.49 h72.83
  text "M" at 2831.75,1172 h72.83
  text "J25" at 2705,921.5 h40
  text "J24" at 2780,921.5 h40
  text "J23" at 2853,921.5 h40
  text "R1" at 3268,921 h40
  text "Phase_Config" at 3525,921.5 h40
  text "R6/R7" at 2967,920.5 h40
  text "R4/R5" at 3077,920.5 h40
  text "R2/R3" at 3188,920.5 h40
  text "1 (4 Phases)" at 3517,871 h40
  text "-" at 2939,869.5 h44
  text "R1" at 3266,869 h40
  text "Y" at 2667,868.5 h44
  text "Y" at 2740,868.5 h44
  text "-" at 3053,868.5 h44
  text "Y" at 2813,867.5 h44
  text "R2" at 3162,867.5 h44
  text "N" at 2668,846.5 h44 r180
  text "2 (3 + 1)" at 3516,823 h40
  text "R1" at 3267,821 h40
  text "R2" at 3162,820.5 h44
  text "Y" at 2813,819.5 h44
  text "R7" at 2938,819.5 h44
  text "-" at 3053,819.5 h44
  text "Y" at 2738,818 h44
  text "N" at 2668,795.33 h44 r180
  text "N" at 2741,795.33 h44 r180
  text "3 (2 + 1 + 1)" at 3519,772 h40
  text "R1" at 3267,768.39 h40
  text "Y" at 2813,767.17 h44
  text "R7" at 2940,767.17 h44
  text "R5" at 3053,767.41 h44
  text "R2" at 3164,767.11 h44
  text "N" at 2666,746.83 h44 r180
  text "N" at 2737,746.83 h44 r180
  text "N" at 2816.62,746.83 h44 r180
  text "4 (1+1+1+1)" at 3520,723.5 h40
  text "R1" at 3267,719.89 h40
  text "R7" at 2938,718.67 h44
  text "R5" at 3054,718.91 h44
  text "R3" at 3163,718.85 h44
  text "N" at 2737,697.38 h44 r180
  text "5 (2 + 2)" at 3521,674.05 h40
  text "R1" at 3266,670.44 h40
  text "Y" at 2664,669.22 h44
  text "Y" at 2813,669.22 h44
  text "R6" at 2936,669.4 h44
  text "R5" at 3053,669.46 h44
  text "R2" at 3165,669.15 h44
  text "JTAG_CON" at 385,375 h55
  text ".Layer_Name" at 576,-859 h60
Top Paste:
  text ".Layer_Name" at 577,-858.49 h60
Bottom Paste:
  text ".Layer_Name" at 577,-858.49 h60
Top Solder:
  text ".Layer_Name" at 577,-858.49 h60
  text ".Layer_Name" at 577,-858.49 h60
Bottom Solder:
  rectangle: 3066,2143 3138,2269
  text ".Layer_Name" at 577,-858.49 h60
Drill Guide:
  text ".Layer_Name" at 577,-858.49 h60
M1 Board Outline:
  lines w7.87: 0,0 0,3448.82 4948.82,3448.82 4948.82,0 0,0
  text ".Layer_Name" at 577,-858.49 h60
M2 Board Dimensions:
  text ".Layer_Name" at 577,-858.49 h60
M3 3D STEP Top:
  text ".Layer_Name" at 577,-858.49 h60
M4 3D STEP Bottom:
  text ".Layer_Name" at 577,-858.49 h60
M5 Assembly Top:
  lines w7: 9870.89,-286.74 10995.89,-286.74 ; 9870.89,-164.24 10993.39,-164.24 ; 10185.89,-406.74 10185.89,-44.24 ; 10570.89,-406.74 9870.89,-406.74 ; 10570.89,-44.24 9870.89,-44.24 ; 9870.89,-406.74 10995.89,-406.74 10995.89,-44.24 9870.89,-44.24 ; 9870.89,-406.74 9870.89,-44.24
  lines w10: -292,-930.17 6308,-930.17 ; -292,-726.83 6310,-726.83 ; -292,-523.5 -292,-1133.5 3713,-1133.5 6310,-1133.5 6310,-523.5 -291.5,-523.5 -291.5,-1133.5 1284,-1133.5 ; 2173,-1133.5 2173,-523.5 ; 3440,-726.83 3440,-523.5 ; 4280,-726.83 4280,-523.5 ; 4902,-1140 4902,-937.17
  text "TABLE 1" at 10258.39,-9.24 h40
  text "Variant" at 9895.89,-119.24 h40
  text "Label text" at 10330.89,-119.24 h40
  text "001" at 9963.39,-239.24 h40
  text "TPS6594EVM" at 10240.89,-241.74 h40
  text "COMPONENTS MARKED 'DNP' SHOULD NOT BE POPULATED, AND MAY NOT BE IN BILL OF MATERIALS" at 1153.5,-318.5 h60
  text "ASSEMBLY VARIANT:" at 1153,-434 h60
  text ".VariantName" at 2189,-434 h60
  text "PCB VIEWED FROM TOP SIDE" at -228.5,-655.67 h60
  text "BOARD #:" at 2248,-655.67 h60
  text ".PRJ_Number" at 2793.5,-655.67 h60
  text "REV:" at 3638,-655.67 h60
  text ".PCB_Rev" at 3929.5,-655.67 h60
  text "SVN REV:" at 4476,-655.67 h60
  text ".VersionControl_RevNumber" at 4982,-655.67 h60
  text "IGNORE ->" at -228.5,-858.49 h60
  text "PLOT NAME =" at -228.5,-1064.34 h60
  text ".plot_File_Name" at 577,-1064.34 h60
  text "GENERATED    :" at 2250,-1064.34 h60
  text ".Print_Date" at 3119.5,-1064.34 h60
  text ".Print_Time" at 3848.5,-1064.34 h60
  text "TEXAS INSTRUMENTS" at 5113,-1064.34 h60
M6 Assembly Bottom:
  lines w10: -292.5,-727.33 6309.5,-727.33 ; -290.5,-930.67 6309.5,-930.67 ; 1115.5,-1140.5 1115.5,-937.67 ; 1737.5,-727.33 1737.5,-524 ; 2577.5,-727.33 2577.5,-524 ; 3844.5,-1134 3844.5,-524 ; 4733.5,-1134 6309,-1134 6309,-524 -292.5,-524 -292.5,-1134 2304.5,-1134 6309.5,-1134 6309.5,-524
  text "COMPONENTS MARKED 'DNP' SHOULD NOT BE POPULATED, AND MAY NOT BE IN BILL OF MATERIALS" at 6102,-318 h60
  text ".VariantName" at 5058,-434 h60
  text "ASSEMBLY VARIANT:" at 6097,-434 h60
  text ".VersionControl_RevNumber" at 1035.5,-656.17 h60
  text "SVN REV:" at 1541.5,-656.17 h60
  text ".PCB_Rev" at 2088,-656.17 h60
  text "REV:" at 2379.5,-656.17 h60
  text ".PRJ_Number" at 3224,-656.17 h60
  text "BOARD #:" at 3769.5,-656.17 h60
  text "PCB VIEWED FROM BOTTOM SIDE" at 6246,-656.17 h60
  text "IGNORE ->" at 2547.85,-858.49 h60
  text "TEXAS INSTRUMENTS" at 904.5,-1064.84 h60
  text ".Print_Time" at 2169,-1064.84 h60
  text ".Print_Date" at 2898,-1064.84 h60
  text "GENERATED    :" at 3767.5,-1064.84 h60
  text ".plot_File_Name" at 5440.5,-1064.84 h60
  text "PLOT NAME =" at 6246,-1064.84 h60
M9 Title Sheet:
  drawing of 57 lines, arcs and shapes, not listed
  text "1" at 739.84,8036.5 h70
  text "2" at 3235.5,8036.5 h70
  text "3" at 5724.84,8036.5 h70
  text "4" at 8231.51,8036.5 h70
  text "5" at 10730.5,8036.5 h70
  text "6" at 13235.5,8036.5 h70
  text "A" at -416.5,6893.5 h70
  text "A" at 14383.5,6893.5 h70
  text "B" at -416.5,4513.5 h70
  text "B" at 14383.5,4513.5 h70
  text "C" at -416.5,2138.5 h70
  text "C" at 14383.5,2138.5 h70
  text "PROJECT TITLE:" at 11343.5,277.5 h45
  text ".PRJ_Title" at 11357,132 h70
  text "DESIGNED FOR:" at 11343.5,-23.5 h45
  text ".PRJ_Customer" at 11393.5,-163.5 h70
  text "D" at -416.5,-231.5 h70
  text "D" at 14383.5,-231.5 h70
  text "FILE NAME:" at 11343.5,-323.5 h45
  text ".PCB_File_Name_No_Path" at 11393.5,-443.5 h70
  text "Texas Instruments (TI) and/or its licensors do not warrant the accuracy or completeness of this specification" at 6374,-605.34 h45
  text "ENGINEER:" at 11343.5,-613.5 h45
  text "LAYOUT BY:" at 12848.5,-613.5 h45
  text "or any information contained therein. TI and/or its licensors do not warrant that this design will meet" at 6329.01,-718 h45
  text ".PRJ_Engineer" at 11393.5,-768.49 h70
  text ".PCB_Layout" at 12899,-768.49 h70
  text "the specifications, will be suitable for your application or fit for any particular purpose, or will operate in" at 6329.01,-830.67 h45
  text ".Layer_Name" at 577,-858.49 h60
  text "ALTIUM DESIGNER VERSION:" at 12848.5,-923.5 h45
  text "an implementation. TI and/or its licensors do not warrant that the design is production worthy. You should" at 6329.01,-943.33 h45
  text "completely validate and test your design implementation to confirm the system functionality for your application." at 6374,-1056 h45
  text ".print_Scale" at 11393.5,-1056.83 h70
  text ".Application_BuildNumber" at 12899,-1056.83 h70
  text "1" at 739.84,-1263.5 h70
  text "2" at 3235.5,-1263.5 h70
  text "3" at 5724.84,-1263.5 h70
  text "4" at 8231.51,-1263.5 h70
  text "5" at 10730.5,-1263.5 h70
  text "6" at 13235.5,-1263.5 h70
M10 Fab Notes:
  drawing of 212 lines, arcs and shapes, not listed
  text "DESIGN INFORMATION" at 12381.02,6810 h60
  text "(REFER ALSO ARRAY/PANEL PROFILING INFORMATION)" at 12019.46,6648.29 h60
  text "BOARD SIZE" at 11333.46,6644 h60
  text "125.7mm" at 11795.78,6516.18 h60
  text "X" at 12301.46,6516.18 h60
  text "87.6mm" at 12532.78,6516.18 h60
  text "Number of Layers :" at 11736.46,6319 h60
  text "6" at 12831.27,6309 h60
  text "MIN. TRACK WIDTH:" at 11736.46,6180 h60
  text "MIL" at 12987.46,6180 h60
  text "4.9" at 12772.64,6179.13 h60
  text "MIN. CLEARANCE:" at 11736.46,6048 h60
  text "4" at 12832.7,6048 h60
  text "MIL" at 12987.46,6048 h60
  text "MIN. VIA PAD SIZE:" at 11736.46,5916 h60
  text "7.8" at 12802.71,5916 h60
  text "MIL" at 12987.46,5916 h60
  text "0.1mm (4MIL)" at 12431.46,5774.29 h60
  text "MINIMUM ANNULAR RING" at 11407.23,5770 h60
  text "EXTERNAL" at 13139.46,5770 h60
  text "PER" at 11607.23,5652 h60
  text "IPC-D-275 CLASS 2 LEVEL C" at 11827.23,5652 h60
  text "MIL, HOLES" at 13315.46,5539.71 h60
  text "+/-" at 12923,5539 h60
  text "+/-" at 13777,5539 h60
  text "REGISTRATION TOLERANCES:" at 11407.23,5534 h60
  text "METAL" at 12607,5534 h60
  text "5" at 13183.2,5534 h60
  text "3" at 14016.2,5534 h60
  text "MIL" at 14132.46,5534 h60
  text "MATERIAL:" at 11332.46,5324.54 h60
  text "FR-4 High Tg" at 12318.9,5184.21 h60
  text "FR-408" at 11753.46,5175.64 h60
  text "X" at 12165.46,5175.64 h60
  text "OTHER" at 13241.46,5175.64 h60
  text "62 MIL (1.6mm) +/-10%" at 12073.56,5012.92 h60
  text "THICKNESS:" at 11407.23,5008.64 h60
  text "OTHER" at 13358.46,5008.64 h60
  text "X" at 11947.46,5004.64 h60
  text "TOLERANCE:" at 11407.23,4850.64 h60
  text "X" at 12246.53,4850.64 h60
  text "ANSI IPC-6012 TYPE 3 CLASS 2" at 12433.48,4850.64 h60
  text "OTHER +/-" at 12433.46,4694.64 h60
  text "BOW & TWIST:" at 11407.23,4537.64 h60
  text "X" at 12246.53,4537.64 h60
  text "ANSI IPC-6012 TYPE 3 CLASS 2" at 12433.48,4537.64 h60
  text "OTHER +/-" at 12433.46,4379.13 h60
  text "COPPER THICKNESS (FINISHED):" at 11332.46,4243.64 h60
  text "1.4MIL (1oz)" at 12212.46,4090.92 h60
  text "2MIL (1.4oz)" at 12979.46,4090.92 h60
  text "2.8MIL (2oz)" at 13706.46,4090.92 h60
  text "OUTER:" at 11689.46,4086.64 h60
  text "X" at 13579,4082 h60
  text "1.4MIL (1oz)" at 12212.46,3933.92 h60
  text "2.8MIL (2oz)" at 12979.46,3933.92 h60
  text "N/A" at 13706,3934.29 h60
  text "INNER SIGNAL:" at 11400.38,3929.64 h60
  text "X" at 12085.42,3929.64 h60
  text "DRILLING:" at 11332.46,3790.64 h60
  text "REFERENCE:" at 11407.23,3673.64 h60
  text "X" at 12055.46,3673.64 h60
  text "AS SHOWN" at 12242.46,3673.64 h60
  text "X" at 12956.46,3673.64 h60
  text "NC_DRILL FILES" at 13093.46,3673.64 h60
  text "PTH MIN COPPER THICKNESS:" at 11407.23,3515.64 h60
  text "X" at 12757.46,3515.64 h60
  text "1MIL" at 12894.46,3515.64 h60
  text "OTHER" at 13391.46,3515.64 h60
  text "BOARD FINISH:" at 11332.46,3356.64 h60
  text "SILKSCREEN:" at 11487.68,3238.64 h60
  text "X" at 12436.46,3238.64 h60
  text "TOP" at 12562.46,3238.64 h60
  text "X" at 12946.46,3238.64 h60
  text "BOTTOM" at 13073.46,3238.64 h60
  text "SILKSCREEN COLOR:" at 11487.68,3071.64 h60
  text "X" at 12435.42,3071.64 h60
  text "WHITE" at 12562.46,3071.64 h60
  text "OTHER" at 13073.46,3071.64 h60
  text "SOLDER RESIST COLOR:" at 11487.68,2901.64 h60
  text "GREEN" at 12182.46,2742.44 h60
  text "X" at 12640,2742.44 h60
  text "BLUE" at 12773.46,2742.44 h60
  text "OTHER" at 13311.46,2742.44 h60
  text "IMMERSION GOLD (ENIG)" at 12393.46,2553.92 h60
  text "ENEPIG" at 13731,2550.64 h60
  text "SURFACE FINISH:" at 11332.46,2549.64 h60
  text "X" at 12206.51,2549.64 h60
  text "IMM. TIN/SILVER OR EQUIV" at 11662,2392.64 h60
  text "OTHER" at 13093.46,2392.64 h60
  text "ARRAY/PANEL:" at 11332.46,2213.64 h60
  text "CUT AND TRIM PER MECH LAYER 1" at 12393.46,2209.35 h60
  text "N.C. ROUTE" at 12393.46,2057.64 h60
  text "V. SCORE" at 13259.46,2057.64 h60
  text "X" at 13070,2048.44 h60
  text "CERTIFICATION:" at 11332.46,1920.64 h60
  text "MATERIALS AND WORKMANSHIP FOR ALL PCBS" at 12057.46,1920.64 h60
  text "TO MEET OR EXCEED THE REQUIREMENTS OF:" at 12057.46,1822.64 h60
  text "X" at 11683.96,1686.13 h60
  text "ANSI IPC-A-600F CLASS ->" at 11822.96,1686.13 h60
  text "X" at 13462.02,1686.13 h60
  text "2" at 13580.96,1686.14 h60
  text "1" at 13265.96,1684.64 h60
  text "3" at 13934.96,1684.64 h60
  text "OTHER" at 13298.3,1534.51 h60
  text "PER ORDER" at 13695.36,1534.51 h60
  text "X" at 11686.02,1526.64 h60
  text "UL 94V-0" at 11822.96,1526.64 h60
  text "X" at 12498.02,1526.64 h60
  text "RoHS" at 12634.96,1526.64 h60
  text "ADDITIONAL REQUIREMENTS:" at 11332.46,1385.64 h60
  text "MICROSECTION:" at 11407.23,1270.64 h60
  text "YES" at 12312.96,1270.64 h60
  text "REQUIRED" at 13193.4,1122.37 h60
  text "PER ORDER" at 13785.4,1119.51 h60
  text "BARE BOARD ELEC. TEST:" at 11407.23,1111.64 h60
  text "NONE" at 12712.96,1111.64 h60
  text "X" at 13047.46,1111.64 h60
  text "METAL" at 13083.71,958.23 h60
  text "X" at 13458.94,957.87 h60
  text "SILK" at 13595.4,958.23 h60
  text "MANUFACTURER'S UL:" at 11407.23,954.64 h60
  text "RAIL" at 12572.96,950.35 h60
  text ".Layer_Name" at 577,-858.49 h60
  text ".Layer_Name" at 577,-858.49 h60
M11 Gerber Information:
  lines w10: -292,-930.17 6308,-930.17 ; -292,-726.83 6310,-726.83 ; -292,-523.5 -292,-1133.5 3713,-1133.5 6310,-1133.5 6310,-523.5 -291.5,-523.5 -291.5,-1133.5 1284,-1133.5 ; 2173,-1133.5 2173,-523.5 ; 3440,-726.83 3440,-523.5 ; 4280,-726.83 4280,-523.5 ; 4902,-1140 4902,-937.17
  text "ALL ARTWORK VIEWED FROM TOP SIDE" at -228.5,-655.67 h60
  text "BOARD #:" at 2248,-655.67 h60
  text ".PRJ_Number" at 2793.5,-655.67 h60
  text "REV:" at 3638,-655.67 h60
  text ".PCB_Rev" at 3929.5,-655.67 h60
  text "SVN REV:" at 4476,-655.67 h60
  text ".VersionControl_RevNumber" at 4982,-655.67 h60
  text "LAYER NAME =" at -228.5,-858.49 h60
  text "PLOT NAME =" at -228.5,-1064.34 h60
  text ".plot_File_Name" at 577,-1064.34 h60
  text "GENERATED    :" at 2250,-1064.34 h60
  text ".Print_Date" at 3119.5,-1064.34 h60
  text ".Print_Time" at 3848.5,-1064.34 h60
  text "TEXAS INSTRUMENTS" at 5113,-1064.34 h60
M12 Stackup:
  drawing of 399 lines, arcs and shapes, not listed
  text "Layer" at 6654.58,6814 h60
  text "Name" at 7064.49,6814 h60
  text "Material" at 8004.23,6814 h60
  text "Thickness" at 8864,6814 h60
  text "Constant" at 9513.84,6814 h60
  text "Board Layer Stack" at 10083.7,6814 h60
  text "1" at 6654.58,6694 h60
  text "Top Overlay" at 7064.49,6694 h60
  text "2" at 6654.58,6574 h60
  text "Top Solder" at 7064.49,6574 h60
  text "Solder Resist" at 8004.23,6574 h60
  text "0.65mil" at 8864,6574 h60
  text "3.5" at 9513.84,6574 h60
  text "3" at 6654.58,6454 h60
  text "Top Layer" at 7064.49,6454 h60
  text "Copper" at 8004.23,6454 h60
  text "2.80mil" at 8864,6454 h60
  text "4" at 6654.58,6334 h60
  text "Dielectric1" at 7064.49,6334 h60
  text "FR-4" at 8004.23,6334 h60
  text "5.00mil" at 8864,6334 h60
  text "4.2" at 9513.84,6334 h60
  text "5" at 6654.58,6214 h60
  text "GND Layer 1" at 7064.49,6214 h60
  text "Copper" at 8004.23,6214 h60
  text "1.40mil" at 8864,6214 h60
  text "6" at 6654.58,6094 h60
  text "Dielectric 2" at 7064.49,6094 h60
  text "FR-4" at 8004.23,6094 h60
  text "5.00mil" at 8864,6094 h60
  text "4.2" at 9513.84,6094 h60
  text "7" at 6654.58,5974 h60
  text "Signal Layer 1" at 7064.49,5974 h60
  text "Copper" at 8004.23,5974 h60
  text "1.40mil" at 8864,5974 h60
  text "8" at 6654.58,5854 h60
  text "Dielectric 3" at 7064.49,5854 h60
  text "FR-4" at 8004.23,5854 h60
  text "29.50mil" at 8864,5854 h60
  text "4.2" at 9513.84,5854 h60
  text "9" at 6654.58,5734 h60
  text "Signal Layer 2" at 7064.49,5734 h60
  text "Copper" at 8004.23,5734 h60
  text "1.40mil" at 8864,5734 h60
  text "10" at 6654.58,5614 h60
  text "Dielectric 4" at 7064.49,5614 h60
  text "FR-4" at 8004.23,5614 h60
  text "5.00mil" at 8864,5614 h60
  text "4.2" at 9513.84,5614 h60
  text "11" at 6654.58,5494 h60
  text "GND Layer 2" at 7064.49,5494 h60
  text "Copper" at 8004.23,5494 h60
  text "1.40mil" at 8864,5494 h60
  text "12" at 6654.58,5374 h60
  text "Dielectric 5" at 7064.49,5374 h60
  text "FR-4" at 8004.23,5374 h60
  text "5.00mil" at 8864,5374 h60
  text "4.2" at 9513.84,5374 h60
  text "13" at 6654.58,5254 h60
  text "Bottom Layer" at 7064.49,5254 h60
  text "Copper" at 8004.23,5254 h60
  text "2.80mil" at 8864,5254 h60
  text "14" at 6654.58,5134 h60
  text "Bottom Solder" at 7064.49,5134 h60
  text "Solder Resist" at 8004.23,5134 h60
  text "0.65mil" at 8864,5134 h60
  text "3.5" at 9513.84,5134 h60
  text "15" at 6654.58,5014 h60
  text "Bottom Overlay" at 7064.49,5014 h60
  text ".Layer_Name" at 577,-858.49 h60
M13 Component Bodies Top:
  text ".Layer_Name" at 577,-858.49 h60
M14 Component Bodies Bottom:
  text ".Layer_Name" at 577,-858.49 h60
M15 Courtyards Top:
  text ".Layer_Name" at 577,-858.49 h60
M16 Courtyards Bottom:
  text ".Layer_Name" at 577,-858.49 h60
Drill Drawing:
  drawing of 160 lines, arcs and shapes, not listed
  text "Symbol" at 6663.39,4825.34 h72
  text "Quantity" at 6963.95,4825.34 h72
  text "Finished Hole Size" at 7295.95,4825.34 h72
  text "Plated" at 7932.52,4825.34 h72
  text "Hole Type" at 8191.66,4825.34 h72
  text "Drill Layer Pair" at 8566.81,4825.34 h72
  text "Hole Tolerance" at 9291.14,4825.34 h72
  text "1" at 6963.95,4701.02 h60
  text "25.59mil (0.650mm)" at 7295.95,4701.02 h60
  text "NPTH" at 7932.52,4701.02 h60
  text "Round" at 8191.66,4701.02 h60
  text "Top Layer - Bottom Layer" at 8566.81,4701.02 h60
  text "2" at 6963.95,4576.7 h60
  text "35.43mil (0.900mm)" at 7295.95,4576.7 h60
  text "NPTH" at 7932.52,4576.7 h60
  text "Round" at 8191.66,4576.7 h60
  text "Top Layer - Bottom Layer" at 8566.81,4576.7 h60
  text "A" at 6638.1,4566.7 h55.25
  text "15" at 6963.95,4452.38 h60
  text "7.87mil (0.200mm)" at 7295.95,4452.38 h60
  text "PTH" at 7932.52,4452.38 h60
  text "Round" at 8191.66,4452.38 h60
  text "Top Layer - Bottom Layer" at 8566.81,4452.38 h60
  text "544" at 6963.95,4328.06 h60
  text "8.00mil (0.203mm)" at 7295.95,4328.06 h60
  text "PTH" at 7932.52,4328.06 h60
  text "Round" at 8191.66,4328.06 h60
  text "Top Layer - Bottom Layer" at 8566.81,4328.06 h60
  text "39" at 6963.95,4203.74 h60
  text "10.00mil (0.254mm)" at 7295.95,4203.74 h60
  text "PTH" at 7932.52,4203.74 h60
  text "Round" at 8191.66,4203.74 h60
  text "Top Layer - Bottom Layer" at 8566.81,4203.74 h60
  text "196" at 6963.95,4079.42 h60
  text "11.00mil (0.279mm)" at 7295.95,4079.42 h60
  text "PTH" at 7932.52,4079.42 h60
  text "Round" at 8191.66,4079.42 h60
  text "Top Layer - Bottom Layer" at 8566.81,4079.42 h60
  text "B" at 6638.1,4069.42 h55.25
  text "21" at 6963.95,3955.1 h60
  text "39.37mil (1.000mm)" at 7295.95,3955.1 h60
  text "PTH" at 7932.52,3955.1 h60
  text "Round" at 8191.66,3955.1 h60
  text "Top Layer - Bottom Layer" at 8566.81,3955.1 h60
  text "77" at 6963.95,3830.78 h60
  text "40.00mil (1.016mm)" at 7295.95,3830.78 h60
  text "PTH" at 7932.52,3830.78 h60
  text "Round" at 8191.66,3830.78 h60
  text "Top Layer - Bottom Layer" at 8566.81,3830.78 h60
  text "41" at 6963.95,3706.46 h60
  text "40.16mil (1.020mm)" at 7295.95,3706.46 h60
  text "PTH" at 7932.52,3706.46 h60
  text "Round" at 8191.66,3706.46 h60
  text "Top Layer - Bottom Layer" at 8566.81,3706.46 h60
  text "2" at 6963.95,3582.14 h60
  text "43.31mil (1.100mm)" at 7295.95,3582.14 h60
  text "PTH" at 7932.52,3582.14 h60
  text "Round" at 8191.66,3582.14 h60
  text "Top Layer - Bottom Layer" at 8566.81,3582.14 h60
  text "17" at 6963.95,3457.82 h60
  text "45.28mil (1.150mm)" at 7295.95,3457.82 h60
  text "PTH" at 7932.52,3457.82 h60
  text "Round" at 8191.66,3457.82 h60
  text "Top Layer - Bottom Layer" at 8566.81,3457.82 h60
  text "12" at 6963.95,3333.5 h60
  text "47.24mil (1.200mm)" at 7295.95,3333.5 h60
  text "PTH" at 7932.52,3333.5 h60
  text "Round" at 8191.66,3333.5 h60
  text "Top Layer - Bottom Layer" at 8566.81,3333.5 h60
  text "25" at 6963.95,3209.18 h60
  text "62.99mil (1.600mm)" at 7295.95,3209.18 h60
  text "PTH" at 7932.52,3209.18 h60
  text "Round" at 8191.66,3209.18 h60
  text "Top Layer - Bottom Layer" at 8566.81,3209.18 h60
  text "4" at 6963.95,3084.86 h60
  text "120.00mil (3.048mm)" at 7295.95,3084.86 h60
  text "PTH" at 7932.52,3084.86 h60
  text "Round" at 8191.66,3084.86 h60
  text "Top Layer - Bottom Layer" at 8566.81,3084.86 h60
  text "1" at 6963.95,2960.54 h60
  text "25.59mil (0.650mm)" at 7295.95,2960.54 h60
  text "NPTH" at 7932.52,2960.54 h60
  text "Slot" at 8191.66,2960.54 h60
  text "Top Layer - Bottom Layer" at 8566.81,2960.54 h60
  text "4" at 6963.95,2836.22 h60
  text "19.69mil (0.500mm)" at 7295.95,2836.22 h60
  text "PTH" at 7932.52,2836.22 h60
  text "Slot" at 8191.66,2836.22 h60
  text "Top Layer - Bottom Layer" at 8566.81,2836.22 h60
  text "1001 Total" at 6963.95,2711.9 h60
  text "Slot definitions :" at 6663.39,2624.87 h60
  text "Routed Path Length" at 7114.1,2624.87 h60
  text "= Calculated from tool start centre position to tool end centre position." at 7653.84,2624.87 h60
  text "Hole Length" at 7114.1,2575.14 h60
  text "= Routed Path Length + Tool Size = Slot length as defined in the PCB layout" at 7454.04,2575.14 h60
  text ".Layer_Name" at 577,-858.49 h60
M20 Hard Gold Plating:
  text ".Layer_Name" at 577,-858.49 h60

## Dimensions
0,0 to 0,3450 on M2 Board Dimensions
0,0 to 4950,0 on M2 Board Dimensions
